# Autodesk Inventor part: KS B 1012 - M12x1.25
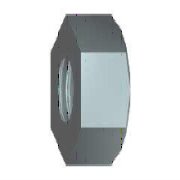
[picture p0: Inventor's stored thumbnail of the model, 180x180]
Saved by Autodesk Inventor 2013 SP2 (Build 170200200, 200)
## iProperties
IsCustomPart: 0
Created: 2009-02
Part Number: KS B 1012 - M12x1.25
Material: 강, 연강
Description: 6각 너트
Document SubType Name: Modeling
Standard: KS B 1012
Designer: KYOUNG IL JANG
Standards Organization: KS
Language: ko-KR
Size Designation: M12x1.25
Categories: <MemberInstance><Categories><Category DisplayName="조임쇠" InternalName="e4da775c-781d-43d5-af7c-5136215cf5a6" Mnemonic="FSTN"><Category DisplayName="너트" InternalN
Density: 1 g/cm^3
Author: KYOUNG IL JANG
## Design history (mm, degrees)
sketch "스케치1"
  geometry: L1 (10.97, 0)-(5.485, -9.5); L2 (5.485, -9.5)-(-5.485, -9.5); L3 (-5.485, -9.5)-(-10.97, 0); L4 (-10.97, 0)-(-5.485, 9.5); L5 (-5.485, 9.5)-(5.485, 9.5); L6 (5.485, 9.5)-(10.97, 0); 2 further points
  constraints: 12 end point, 1 coincident, 1 horizontal, 11 other
  dimensions: "d0" = 21.93931 distance of L1.start L3.end (= 1.1547 x SW)
extrude "본체" new body sketch "스케치1" distance "d1" = 10 (= KOH); taper "d2" = 0 deg
sketch "스케치2"
  geometry: 1 further point
hole "스레드" sketch "스케치2" diameter "d6" = 10.647; stored, may be unused: countersink angle "d10" = 82 deg, drill point angle "d12" = 118 deg; dims "d7" = 12.7, "d8" = 9.525, "d9" = 6.35, "d11" = 19.05
sketch "스케치3"
  geometry: L1 (0, 10.97)-(10, 10.97) reference; L2 (10, 5.485)-(10, 10.97) reference; L3 (-2, 0)-(12, 0) reference; L4 (9.151, 10.97)-(10, 9.5)
  constraints: 2 end point, 2 point on line
  dimensions: "d3" = 19 diameter of L4.end L3 (= SW01); "d4" = 30 deg angle of L2 L4 (= ANG2)
revolve "모따기3" sketch "스케치3" stored, may be unused: angle "d5" = 90 deg
workaxis "Work Axis1"
workplane "Work Plane1"
body "Solid1"
chamfer "모따기1" distance "d13" = 0.67658 (= -0.5 x GD1 + 0.5 x NND); stored, may be unused: angle "d14" = 30 deg, second distance "d21" = 0.67658 (= -0.5 x GD1 + 0.5 x NND)
chamfer "모따기2" distance "d15" = 0.67658 (= -0.5 x GD1 + 0.5 x NND); stored, may be unused: angle "d16" = 30 deg, second distance "d22" = 0.67658 (= -0.5 x GD1 + 0.5 x NND)
other parameters: "ANG2" = 30 deg [user parameter; used in 1 equation term], "NND" = 12 [user parameter; used in 4 equation terms], "KOH" = 10 [user parameter; used in 1 equation term], "SW" = 19 [user parameter; used in 3 equation terms], "SW01" = 19 (= SW) [user parameter; used in 1 equation term], "GD1" = 10.64684 (computed from THREADDIA, PTC, TOA) [user parameter; used in 4 equation terms], "d19" = 0, "d20" = 0, "d24" = 0, "d25" = 0, "GUL" = 0.67658 (= 0.541266 x PTC) [user parameter], "TPU" = 8 (computed from PTC) [user parameter], "TOA" = 30 deg [user parameter; used in 1 equation term], "PTC" = 1.25 [user parameter; used in 4 equation terms], "E0" = 21.945 (= 1.155 x SW) [user parameter], "THREADDIA" = 12 [user parameter; used in 1 equation term], "GAL" = 0.67658 (= 0.541266 x PTC) [user parameter]
